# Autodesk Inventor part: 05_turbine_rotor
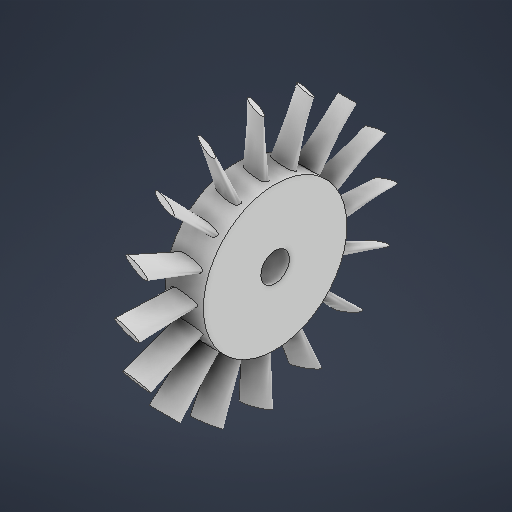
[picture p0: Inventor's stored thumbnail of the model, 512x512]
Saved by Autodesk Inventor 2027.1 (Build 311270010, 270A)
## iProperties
Created: 2026-10
Part Number: 05_turbine_rotor
Material: Generic
Document SubType Name: Modeling
Designer: BHAVAN KUMAR
Density: 1 g/cm^3
Appearance: Default
Author: BHAVAN KUMAR
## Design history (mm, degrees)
sketch "Sketch1"
  geometry: C1 r 30 at (0, 0); C2 r 6 at (0, 0)
  constraints: 2 centre point
  dimensions: "d0" = 60 diameter of C1; "d1" = 12 diameter of C2
extrude "Hub" join sketch "Sketch1" distance "d2" = 16; taper "d3" = 0 deg
workplane "Work Plane3"
sketch "Sketch4"
  geometry: C1 r 10 at (-8, 0)
  constraints: 1 centre point
workplane "Work Plane4"
sketch "Sketch5"
  geometry: C1 r 9.397 at (-8, 0)
  constraints: 1 centre point
feature "Blade_Loft" sketch "Sketch5" dims "d15" = 0, "d16" = 90 deg, "d17" = 0, "d18" = 90 deg
pattern_circular "Blade_Pattern" dims angle "d20" = 360 deg
body "Solid1"
other parameters: "hub_bore" = 12 [user parameter], "hub_len" = 16 [user parameter], "blade_embed" = 2 [user parameter], "blade_tip_r" = 54 [user parameter], "blade_twist" = -20 deg [user parameter], "d13" = 8, "d14" = 54
